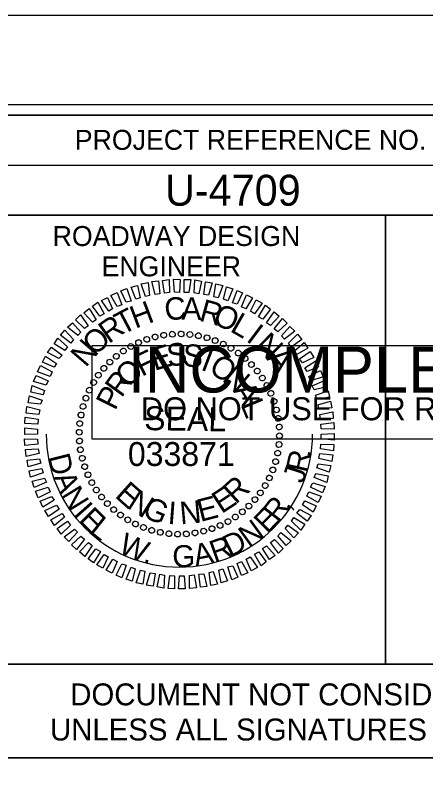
# Model space of a CAD drawing. Extents: x 1779926 to 1781610, y 620464 to 621564.
# Drawn here: x 1781400.2 to 1781503, y 621371.7 to 621564.2 of the extents above; entities that cross this region are included whole.
import ezdxf

# ---------------------------------------------------------------- set-up
doc = ezdxf.new("R2010")
doc.units = 0
for name, color, linetype in [('Old_Level_58', 7, 'Continuous'), ('Scratch_Level_0', 7, 'Continuous'), ('Sheet Cutting Line CELL', 7, 'Continuous'), ('Sheet Data Field CELL', 7, 'Continuous'), ('Sheet Plot Border Inside CELL', 7, 'Continuous'), ('Sheet Plot Border Outside CELL', 7, 'Continuous'), ('Sheet Professional Seal CELL', 7, 'Continuous'), ('Sheet Profile CELL', 7, 'Continuous'), ('Sheet Profile Grid Major CELL', 7, 'Continuous'), ('Sheet Profile Grid Minor CELL', 7, 'Continuous'), ('Sheet Sticker Exception Certification CELL', 7, 'Continuous'), ('Sheet Sticker Incomplete CELL', 7, 'Continuous')]:
    doc.layers.add(name, color=color, linetype=linetype)

msp = doc.modelspace()

# ---------------------------------------------------------------- linework, layer by layer
at = {"layer": 'Old_Level_58'}
msp.add_lwpolyline([(1781392.96, 621378.13), (1781592.95, 621378.13), (1781592.95, 621314.19), (1781392.96, 621314.19)], close=True, dxfattribs=at)
at = {"layer": 'Scratch_Level_0'}
msp.add_arc((1781441.32, 621459.29), 33.36, 180, 360, dxfattribs=at)
at = {"layer": 'Sheet Cutting Line CELL'}
msp.add_line((1781609.96, 621564.19), (1779925.96, 621564.19), dxfattribs=at)
at = {"layer": 'Sheet Plot Border Inside CELL'}
msp.add_lwpolyline([(1779938.96, 620486.64), (1781605.46, 620486.64), (1781605.46, 621541.74), (1779938.96, 621541.74)], close=True, dxfattribs=at)
at = {"layer": 'Sheet Plot Border Outside CELL'}
msp.add_lwpolyline([(1779925.96, 620464.19), (1781609.96, 620464.19), (1781609.96, 621564.19), (1779925.96, 621564.19)], close=True, dxfattribs=at)
at = {"layer": 'Sheet Professional Seal CELL'}
for p, q in [((1781439.57, 621484.34), (1781439.57, 621484.34)), ((1781441.77, 621484.39), (1781441.77, 621484.39)), ((1781433.12, 621483.04), (1781433.12, 621483.04)), ((1781435.22, 621483.64), (1781435.22, 621483.64)), ((1781437.42, 621484.04), (1781437.42, 621484.04)), ((1781443.97, 621484.24), (1781443.97, 621484.24)), ((1781446.12, 621483.89), (1781446.12, 621483.89)), ((1781448.22, 621483.44), (1781448.22, 621483.44)), ((1781450.32, 621482.74), (1781450.32, 621482.74)), ((1781429.17, 621481.24), (1781429.17, 621481.24)), ((1781431.12, 621482.24), (1781431.12, 621482.24)), ((1781452.32, 621481.84), (1781452.32, 621481.84)), ((1781454.27, 621480.84), (1781454.27, 621480.84)), ((1781425.52, 621478.84), (1781425.52, 621478.84)), ((1781427.27, 621480.09), (1781427.27, 621480.09)), ((1781456.07, 621479.59), (1781456.07, 621479.59)), ((1781423.87, 621477.34), (1781423.87, 621477.34)), ((1781457.82, 621478.24), (1781457.82, 621478.24)), ((1781459.37, 621476.74), (1781459.37, 621476.74)), ((1781422.37, 621475.79), (1781422.37, 621475.79)), ((1781460.87, 621475.09), (1781460.87, 621475.09)), ((1781421.02, 621474.04), (1781421.02, 621474.04)), ((1781462.12, 621473.34), (1781462.12, 621473.34)), ((1781419.77, 621472.24), (1781419.77, 621472.24)), ((1781463.27, 621471.44), (1781463.27, 621471.44)), ((1781418.77, 621470.29), (1781418.77, 621470.29)), ((1781464.27, 621469.49), (1781464.27, 621469.49)), ((1781417.87, 621468.29), (1781417.87, 621468.29)), ((1781465.07, 621467.49), (1781465.07, 621467.49)), ((1781417.17, 621466.19), (1781417.17, 621466.19)), ((1781465.67, 621465.39), (1781465.67, 621465.39)), ((1781416.72, 621464.09), (1781416.72, 621464.09)), ((1781466.07, 621463.19), (1781466.07, 621463.19)), ((1781416.37, 621461.94), (1781416.37, 621461.94)), ((1781416.22, 621459.74), (1781416.22, 621459.74)), ((1781466.37, 621461.04), (1781466.37, 621461.04)), ((1781416.27, 621457.54), (1781416.27, 621457.54)), ((1781441.32, 621459.29), (1781441.32, 621459.29)), ((1781466.42, 621458.84), (1781466.42, 621458.84)), ((1781466.27, 621456.64), (1781466.27, 621456.64)), ((1781416.57, 621455.39), (1781416.57, 621455.39)), ((1781465.92, 621454.49), (1781465.92, 621454.49)), ((1781416.97, 621453.19), (1781416.97, 621453.19)), ((1781465.47, 621452.39), (1781465.47, 621452.39)), ((1781417.57, 621451.09), (1781417.57, 621451.09)), ((1781464.77, 621450.29), (1781464.77, 621450.29)), ((1781418.37, 621449.09), (1781418.37, 621449.09)), ((1781463.87, 621448.29), (1781463.87, 621448.29)), ((1781419.37, 621447.14), (1781419.37, 621447.14)), ((1781462.87, 621446.34), (1781462.87, 621446.34)), ((1781420.52, 621445.24), (1781420.52, 621445.24)), ((1781461.62, 621444.54), (1781461.62, 621444.54)), ((1781421.77, 621443.49), (1781421.77, 621443.49)), ((1781460.27, 621442.79), (1781460.27, 621442.79)), ((1781423.27, 621441.84), (1781423.27, 621441.84)), ((1781424.82, 621440.34), (1781424.82, 621440.34)), ((1781458.77, 621441.24), (1781458.77, 621441.24)), ((1781426.57, 621438.99), (1781426.57, 621438.99)), ((1781455.37, 621438.49), (1781455.37, 621438.49)), ((1781457.12, 621439.74), (1781457.12, 621439.74)), ((1781428.37, 621437.74), (1781428.37, 621437.74)), ((1781430.32, 621436.74), (1781430.32, 621436.74)), ((1781451.52, 621436.34), (1781451.52, 621436.34)), ((1781453.47, 621437.34), (1781453.47, 621437.34)), ((1781432.32, 621435.84), (1781432.32, 621435.84)), ((1781434.42, 621435.14), (1781434.42, 621435.14)), ((1781436.52, 621434.69), (1781436.52, 621434.69)), ((1781438.67, 621434.34), (1781438.67, 621434.34)), ((1781445.22, 621434.54), (1781445.22, 621434.54)), ((1781447.42, 621434.94), (1781447.42, 621434.94)), ((1781449.52, 621435.54), (1781449.52, 621435.54)), ((1781440.87, 621434.19), (1781440.87, 621434.19)), ((1781443.07, 621434.24), (1781443.07, 621434.24))]:
    msp.add_line(p, q, dxfattribs=at)
for points in [[(1781437.62, 621494.59), (1781437.07, 621497.79), (1781438.77, 621497.99), (1781438.82, 621494.74)], [(1781440.12, 621494.84), (1781439.87, 621498.09), (1781441.52, 621498.04), (1781441.32, 621494.79)], [(1781442.52, 621494.79), (1781442.52, 621498.04), (1781444.17, 621497.99), (1781443.72, 621494.74)], [(1781445.02, 621494.64), (1781445.22, 621497.89), (1781446.87, 621497.59), (1781446.22, 621494.44)], [(1781430.42, 621493.09), (1781429.27, 621496.09), (1781430.82, 621496.54), (1781431.47, 621493.44)], [(1781432.82, 621493.74), (1781431.77, 621496.89), (1781433.47, 621497.24), (1781433.87, 621493.99)], [(1781435.22, 621494.29), (1781434.42, 621497.49), (1781436.07, 621497.64), (1781436.42, 621494.44)], [(1781447.42, 621494.24), (1781447.87, 621497.44), (1781449.52, 621497.19), (1781448.62, 621494.09)], [(1781449.97, 621493.69), (1781450.47, 621496.94), (1781452.17, 621496.54), (1781451.02, 621493.44)], [(1781452.37, 621493.04), (1781453.12, 621496.14), (1781454.67, 621495.64), (1781453.42, 621492.69)], [(1781425.77, 621491.24), (1781424.17, 621494.04), (1781425.72, 621494.74), (1781426.87, 621491.69)], [(1781427.97, 621492.29), (1781426.67, 621495.19), (1781428.17, 621495.79), (1781429.22, 621492.59)], [(1781454.62, 621492.14), (1781455.77, 621495.29), (1781457.17, 621494.69), (1781455.77, 621491.79)], [(1781456.87, 621491.19), (1781458.12, 621494.14), (1781459.67, 621493.44), (1781457.97, 621490.64)], [(1781421.42, 621488.79), (1781419.57, 621491.34), (1781420.87, 621492.29), (1781422.52, 621489.39)], [(1781423.62, 621490.04), (1781421.77, 621492.74), (1781423.32, 621493.54), (1781424.57, 621490.64)], [(1781459.17, 621490.04), (1781460.52, 621492.89), (1781462.02, 621492.04), (1781460.12, 621489.44)], [(1781419.52, 621487.29), (1781417.37, 621489.69), (1781418.72, 621490.74), (1781420.47, 621487.94)], [(1781461.12, 621488.69), (1781462.87, 621491.59), (1781464.17, 621490.54), (1781462.22, 621488.09)], [(1781417.52, 621485.74), (1781415.32, 621487.94), (1781416.52, 621489.14), (1781418.47, 621486.44)], [(1781463.17, 621487.19), (1781465.02, 621489.94), (1781466.32, 621488.84), (1781464.12, 621486.49)], [(1781465.07, 621485.64), (1781467.12, 621488.24), (1781468.32, 621487.04), (1781466.02, 621484.89)], [(1781415.87, 621483.99), (1781413.32, 621486.04), (1781414.57, 621487.19), (1781416.67, 621484.79)], [(1781414.12, 621482.09), (1781411.52, 621484.04), (1781412.62, 621485.34), (1781414.82, 621482.99)], [(1781466.87, 621483.89), (1781469.02, 621486.24), (1781470.22, 621485.04), (1781467.62, 621483.09)], [(1781468.62, 621482.09), (1781470.92, 621484.34), (1781471.97, 621482.99), (1781469.32, 621481.09)], [(1781412.62, 621480.19), (1781409.92, 621481.89), (1781410.87, 621483.34), (1781413.27, 621481.14)], [(1781411.12, 621478.19), (1781408.32, 621479.69), (1781409.32, 621481.09), (1781411.92, 621479.09)], [(1781470.12, 621480.14), (1781472.57, 621482.24), (1781473.52, 621480.79), (1781470.72, 621479.19)], [(1781409.92, 621476.04), (1781407.07, 621477.29), (1781407.82, 621478.84), (1781410.52, 621476.99)], [(1781471.42, 621478.09), (1781474.07, 621479.99), (1781475.02, 621478.49), (1781472.12, 621477.09)], [(1781472.72, 621475.89), (1781475.52, 621477.64), (1781476.17, 621476.09), (1781473.32, 621474.94)], [(1781408.92, 621473.74), (1781405.82, 621474.89), (1781406.57, 621476.44), (1781409.42, 621474.84)], [(1781473.72, 621473.74), (1781476.67, 621475.24), (1781477.32, 621473.64), (1781474.22, 621472.64)], [(1781407.92, 621471.54), (1781404.82, 621472.44), (1781405.47, 621473.99), (1781408.47, 621472.59)], [(1781407.17, 621469.14), (1781404.07, 621469.79), (1781404.42, 621471.44), (1781407.57, 621470.19)], [(1781474.62, 621471.39), (1781477.67, 621472.69), (1781478.22, 621471.14), (1781475.12, 621470.34)], [(1781475.42, 621468.99), (1781478.62, 621470.14), (1781478.92, 621468.49), (1781475.77, 621467.94)], [(1781406.52, 621466.74), (1781403.42, 621467.14), (1781403.77, 621468.84), (1781406.92, 621467.79)], [(1781476.02, 621466.59), (1781479.17, 621467.54), (1781479.47, 621465.84), (1781476.32, 621465.54)], [(1781406.12, 621464.19), (1781402.92, 621464.49), (1781403.12, 621466.19), (1781406.37, 621465.39)], [(1781405.87, 621461.79), (1781402.62, 621461.89), (1781402.72, 621463.54), (1781405.97, 621462.99)], [(1781476.47, 621464.19), (1781479.72, 621464.89), (1781479.87, 621463.19), (1781476.67, 621462.99)], [(1781476.77, 621461.79), (1781480.02, 621462.19), (1781480.12, 621460.49), (1781476.87, 621460.59)], [(1781405.82, 621459.29), (1781402.57, 621459.14), (1781402.57, 621460.84), (1781405.82, 621460.49)], [(1781476.82, 621459.29), (1781480.07, 621459.44), (1781480.07, 621457.74), (1781476.82, 621458.09)], [(1781405.87, 621456.79), (1781402.62, 621456.39), (1781402.52, 621458.09), (1781405.77, 621457.99)], [(1781406.17, 621454.39), (1781402.92, 621453.69), (1781402.77, 621455.39), (1781405.97, 621455.59)], [(1781476.77, 621456.79), (1781480.02, 621456.69), (1781479.92, 621455.04), (1781476.67, 621455.59)], [(1781476.52, 621454.39), (1781479.72, 621454.09), (1781479.52, 621452.39), (1781476.27, 621453.19)], [(1781406.62, 621451.99), (1781403.47, 621451.04), (1781403.17, 621452.74), (1781406.32, 621453.04)], [(1781476.12, 621451.84), (1781479.22, 621451.44), (1781478.87, 621449.74), (1781475.72, 621450.79)], [(1781407.22, 621449.59), (1781404.02, 621448.44), (1781403.72, 621450.09), (1781406.87, 621450.64)], [(1781408.02, 621447.19), (1781404.97, 621445.89), (1781404.42, 621447.44), (1781407.52, 621448.24)], [(1781475.47, 621449.44), (1781478.57, 621448.79), (1781478.22, 621447.14), (1781475.07, 621448.39)], [(1781408.92, 621444.84), (1781405.97, 621443.34), (1781405.32, 621444.94), (1781408.42, 621445.94)], [(1781474.72, 621447.04), (1781477.82, 621446.14), (1781477.17, 621444.59), (1781474.17, 621445.99)], [(1781473.72, 621444.84), (1781476.82, 621443.69), (1781476.07, 621442.14), (1781473.22, 621443.74)], [(1781409.92, 621442.69), (1781407.12, 621440.94), (1781406.47, 621442.49), (1781409.32, 621443.64)], [(1781472.72, 621442.54), (1781475.57, 621441.29), (1781474.82, 621439.74), (1781472.12, 621441.59)], [(1781411.22, 621440.49), (1781408.57, 621438.59), (1781407.62, 621440.09), (1781410.52, 621441.49)], [(1781471.52, 621440.39), (1781474.32, 621438.89), (1781473.32, 621437.49), (1781470.72, 621439.49)], [(1781412.52, 621438.44), (1781410.07, 621436.34), (1781409.12, 621437.79), (1781411.92, 621439.39)], [(1781470.02, 621438.39), (1781472.72, 621436.69), (1781471.77, 621435.24), (1781469.37, 621437.44)], [(1781414.02, 621436.49), (1781411.72, 621434.24), (1781410.67, 621435.59), (1781413.32, 621437.49)], [(1781468.52, 621436.49), (1781471.12, 621434.54), (1781470.02, 621433.24), (1781467.82, 621435.59)], [(1781415.77, 621434.69), (1781413.62, 621432.34), (1781412.42, 621433.54), (1781415.02, 621435.49)], [(1781466.77, 621434.59), (1781469.32, 621432.54), (1781468.07, 621431.39), (1781465.97, 621433.79)], [(1781417.57, 621432.94), (1781415.52, 621430.34), (1781414.32, 621431.54), (1781416.62, 621433.69)], [(1781465.12, 621432.84), (1781467.32, 621430.64), (1781466.12, 621429.44), (1781464.17, 621432.14)], [(1781419.47, 621431.39), (1781417.62, 621428.64), (1781416.32, 621429.74), (1781418.52, 621432.09)], [(1781421.52, 621429.89), (1781419.77, 621426.99), (1781418.47, 621428.04), (1781420.42, 621430.49)], [(1781463.12, 621431.29), (1781465.27, 621428.89), (1781463.92, 621427.84), (1781462.17, 621430.64)], [(1781423.47, 621428.54), (1781422.12, 621425.69), (1781420.62, 621426.54), (1781422.52, 621429.14)], [(1781459.02, 621428.54), (1781460.87, 621425.84), (1781459.32, 621425.04), (1781458.07, 621427.94)], [(1781461.22, 621429.79), (1781463.07, 621427.24), (1781461.77, 621426.29), (1781460.12, 621429.19)], [(1781425.77, 621427.39), (1781424.52, 621424.44), (1781422.97, 621425.14), (1781424.67, 621427.94)], [(1781428.02, 621426.44), (1781426.87, 621423.29), (1781425.47, 621423.89), (1781426.87, 621426.79)], [(1781456.87, 621427.34), (1781458.47, 621424.54), (1781456.92, 621423.84), (1781455.77, 621426.89)], [(1781430.27, 621425.54), (1781429.52, 621422.44), (1781427.97, 621422.94), (1781429.22, 621425.89)], [(1781432.67, 621424.89), (1781432.17, 621421.64), (1781430.47, 621422.04), (1781431.62, 621425.14)], [(1781449.82, 621424.84), (1781450.87, 621421.69), (1781449.17, 621421.34), (1781448.77, 621424.59)], [(1781452.22, 621425.49), (1781453.37, 621422.49), (1781451.82, 621422.04), (1781451.17, 621425.14)], [(1781454.67, 621426.29), (1781455.97, 621423.39), (1781454.47, 621422.79), (1781453.42, 621425.99)], [(1781435.22, 621424.34), (1781434.77, 621421.14), (1781433.12, 621421.39), (1781434.02, 621424.49)], [(1781437.62, 621423.94), (1781437.42, 621420.69), (1781435.77, 621420.99), (1781436.42, 621424.14)], [(1781440.12, 621423.79), (1781440.12, 621420.54), (1781438.47, 621420.59), (1781438.92, 621423.84)], [(1781442.52, 621423.74), (1781442.77, 621420.49), (1781441.12, 621420.54), (1781441.32, 621423.79)], [(1781445.02, 621423.99), (1781445.57, 621420.79), (1781443.87, 621420.59), (1781443.82, 621423.84)], [(1781447.42, 621424.29), (1781448.22, 621421.09), (1781446.57, 621420.94), (1781446.22, 621424.14)]]:
    msp.add_lwpolyline(points, close=True, dxfattribs=at)
for centre, major_axis in [((1781435.25, 621483.62), (-0.174, 0.699)), ((1781437.39, 621484.06), (-0.113, 0.711)), ((1781439.57, 621484.31), (-0.05, 0.718)), ((1781441.75, 621484.36), (0.013, 0.72)), ((1781443.94, 621484.23), (0.075, 0.716)), ((1781446.1, 621483.91), (0.137, 0.707)), ((1781431.11, 621482.2), (-0.293, 0.658)), ((1781433.15, 621483), (-0.234, 0.681)), ((1781448.23, 621483.4), (0.198, 0.692)), ((1781450.3, 621482.7), (0.258, 0.672)), ((1781452.31, 621481.83), (0.316, 0.647)), ((1781427.29, 621480.08), (-0.403, 0.597)), ((1781429.16, 621481.22), (-0.349, 0.63)), ((1781454.23, 621480.78), (0.371, 0.617)), ((1781425.53, 621478.78), (-0.453, 0.56)), ((1781456.06, 621479.58), (0.423, 0.582)), ((1781457.77, 621478.22), (0.472, 0.543)), ((1781423.89, 621477.33), (-0.5, 0.518)), ((1781459.36, 621476.71), (0.518, 0.5)), ((1781421.03, 621474.03), (-0.582, 0.423)), ((1781422.39, 621475.74), (-0.543, 0.472)), ((1781460.81, 621475.07), (0.56, 0.453)), ((1781419.82, 621472.2), (-0.617, 0.371)), ((1781462.11, 621473.31), (0.597, 0.403)), ((1781418.77, 621470.28), (-0.647, 0.316)), ((1781463.25, 621471.45), (0.63, 0.349)), ((1781417.9, 621468.28), (-0.672, 0.258)), ((1781464.23, 621469.49), (0.658, 0.293)), ((1781417.21, 621466.2), (-0.692, 0.198)), ((1781465.03, 621467.45), (0.681, 0.234)), ((1781465.65, 621465.35), (0.699, 0.174)), ((1781416.7, 621464.07), (-0.707, 0.137)), ((1781466.09, 621463.21), (0.711, 0.113)), ((1781416.37, 621461.91), (-0.716, 0.075)), ((1781466.33, 621461.04), (0.718, 0.05)), ((1781416.24, 621459.72), (-0.72, 0.013)), ((1781466.39, 621458.85), (0.72, -0.013)), ((1781416.3, 621457.54), (-0.718, -0.05)), ((1781466.26, 621456.67), (0.716, -0.075)), ((1781416.54, 621455.36), (-0.711, -0.113)), ((1781416.98, 621453.22), (-0.699, -0.174)), ((1781465.93, 621454.5), (0.707, -0.137)), ((1781417.6, 621451.12), (-0.681, -0.234)), ((1781465.42, 621452.37), (0.692, -0.198)), ((1781418.4, 621449.09), (-0.658, -0.293)), ((1781464.73, 621450.3), (0.672, -0.258)), ((1781419.38, 621447.13), (-0.63, -0.349)), ((1781463.86, 621448.29), (0.647, -0.316)), ((1781420.52, 621445.26), (-0.597, -0.403)), ((1781462.81, 621446.37), (0.617, -0.371)), ((1781421.82, 621443.5), (-0.56, -0.453)), ((1781461.61, 621444.55), (0.582, -0.423)), ((1781423.27, 621441.87), (-0.518, -0.5)), ((1781458.74, 621441.25), (0.5, -0.518)), ((1781460.24, 621442.83), (0.543, -0.472)), ((1781424.86, 621440.36), (-0.472, -0.543)), ((1781457.1, 621439.8), (0.453, -0.56)), ((1781426.57, 621439), (-0.423, -0.582)), ((1781428.4, 621437.79), (-0.371, -0.617)), ((1781453.47, 621437.35), (0.349, -0.63)), ((1781455.34, 621438.49), (0.403, -0.597)), ((1781430.32, 621436.75), (-0.316, -0.647)), ((1781432.33, 621435.87), (-0.258, -0.672)), ((1781449.48, 621435.57), (0.234, -0.681)), ((1781451.52, 621436.38), (0.293, -0.658)), ((1781434.4, 621435.18), (-0.198, -0.692)), ((1781436.53, 621434.67), (-0.137, -0.707)), ((1781438.69, 621434.34), (-0.075, -0.716)), ((1781440.88, 621434.21), (-0.013, -0.72)), ((1781443.07, 621434.27), (0.05, -0.718)), ((1781445.24, 621434.52), (0.113, -0.711)), ((1781447.38, 621434.95), (0.174, -0.699))]:
    msp.add_ellipse(centre, major_axis=major_axis, ratio=0.999708, dxfattribs=at)
at = {"layer": 'Sheet Profile CELL'}
for p, q in [((1781392.91, 621526.64), (1781592.96, 621526.64)), ((1781492.96, 621514.14), (1781492.96, 621401.69))]:
    msp.add_line(p, q, dxfattribs=at)
for points in [[(1781592.96, 621539.19), (1780092.96, 621539.19), (1780092.96, 620489.19), (1781592.96, 620489.19)], [(1781392.91, 621539.19), (1781592.96, 621539.19), (1781592.96, 621514.14), (1781392.91, 621514.14)], [(1781392.91, 621514.14), (1781492.96, 621514.14), (1781492.96, 621401.64), (1781392.91, 621401.64)], [(1781492.96, 621514.14), (1781592.96, 621514.14), (1781592.96, 621401.64), (1781492.96, 621401.64)]]:
    msp.add_lwpolyline(points, close=True, dxfattribs=at)
at = {"layer": 'Sheet Profile Grid Major CELL'}
msp.add_lwpolyline([(1781142.96, 621039.19), (1781192.96, 621039.19), (1781192.96, 621539.19), (1781242.96, 621539.19), (1781242.96, 621039.19), (1781292.96, 621039.19), (1781292.96, 621539.19), (1781342.96, 621539.19), (1781342.96, 621039.19), (1781392.96, 621039.19), (1781392.96, 621539.19), (1781419.26, 621539.19)], dxfattribs=at)
at = {"layer": 'Sheet Sticker Exception Certification CELL'}
for p, q in [((1781392.91, 621401.64), (1781592.95, 621401.64)), ((1781392.91, 621401.64), (1781592.95, 621401.64)), ((1781592.95, 621378.14), (1781392.91, 621378.14)), ((1781592.95, 621378.14), (1781392.91, 621378.14))]:
    msp.add_line(p, q, dxfattribs=at)
at = {"layer": 'Sheet Sticker Incomplete CELL'}
msp.add_lwpolyline([(1781419.48, 621457.99), (1781419.48, 621481.49), (1781566.48, 621481.49), (1781566.48, 621457.99)], close=True, dxfattribs=at)

# ---------------------------------------------------------------- texts
at = {"layer": 'Sheet Data Field CELL'}
msp.add_text('U-4709', height=7.75, dxfattribs=at).set_placement((1781437.72, 621516.5))
at = {"layer": 'Sheet Professional Seal CELL'}
for s, height, rotation, p in [('H', 5.64, 20.6195, (1781430.27, 621485.64)), ('C', 5.64, 6.2199, (1781437.87, 621487.64)), ('A', 5.64, 359.0203, (1781441.82, 621487.94)), ('R', 5.64, 344.6211, (1781446.02, 621487.74)), ('T', 5.64, 27.8198, (1781427.02, 621483.99)), ('O', 5.64, 337.4212, (1781449.37, 621486.99)), ('R', 5.64, 35.0205, (1781423.62, 621481.79)), ('L', 5.64, 330.2209, (1781453.77, 621485.14)), ('I', 5.64, 323.0201, (1781457.82, 621482.74)), ('O', 5.64, 42.2217, (1781420.17, 621478.69)), ('N', 5.64, 315.8189, (1781459.97, 621481.19)), ('N', 5.64, 49.4235, (1781417.87, 621475.79)), ('F', 5.64, 25.967, (1781431.87, 621473.59)), ('E', 5.64, 16.6111, (1781435.07, 621475.09)), ('S', 5.64, 7.2556, (1781438.52, 621476.14)), ('S', 5.64, 357.9004, (1781442.12, 621476.19)), ('I', 5.64, 339.1896, (1781446.42, 621475.49)), ('O', 5.64, 329.8335, (1781448.42, 621474.79)), ('A', 5.64, 308.6172, (1781462.92, 621478.24)), ('O', 5.64, 44.6812, (1781428.57, 621470.64)), ('N', 5.64, 320.4766, (1781451.77, 621472.79)), ('R', 5.64, 54.0397, (1781426.82, 621468.19)), ('P', 5.64, 63.3989, (1781425.22, 621464.99)), ('A', 5.64, 301.7603, (1781454.62, 621470.19)), ('L', 5.64, 292.4008, (1781456.57, 621466.74)), ('SEAL', 5.998, 359, (1781432.47, 621460.29)), ('R', 5.64, 42.4814, (1781455.42, 621441.54)), ('E', 5.64, 318.2769, (1781424.92, 621443.64)), ('E', 5.64, 33.1241, (1781451.87, 621439.19)), ('N', 5.64, 327.634, (1781427.92, 621440.94)), ('G', 5.64, 336.9902, (1781431.72, 621438.69)), ('I', 5.64, 355.7012, (1781438.27, 621436.79)), ('N', 5.64, 5.0564, (1781441.62, 621436.64)), ('E', 5.64, 14.4118, (1781446.57, 621437.24))]:
    msp.add_text(s, height=height, rotation=rotation, dxfattribs=at).set_placement(p)
at = {"layer": 'Sheet Profile CELL'}
for s, height, p in [('PROJECT REFERENCE NO.', 5.0001, (1781415.12, 621530.5)), ('ROADWAY DESIGN', 5.0001, (1781409.57, 621506.4)), ('ENGINEER', 5, (1781421.82, 621498.8))]:
    msp.add_text(s, height=height, dxfattribs=at).set_placement(p)
at = {"layer": 'Sheet Profile Grid Minor CELL'}
msp.add_text('033871', height=5.998, dxfattribs=at).set_placement((1781428.42, 621451.28))
for s, rotation, p in [('D', 284.2682, (1781408.32, 621453.64)), ('R', 77.3541, (1781473.29, 621449.39)), ('.', 84.2805, (1781474.25, 621453.31)), ('J', 72.4855, (1781472.33, 621446.71)), ('A', 293.4128, (1781409.64, 621448.47)), ('N', 301.5986, (1781411.5, 621444.07)), ('I', 311.5304, (1781414.57, 621439.16)), ('R', 52.3788, (1781466.12, 621436.81)), ('E', 315.0508, (1781415.86, 621437.56)), ('E', 45.7958, (1781463.38, 621434.12)), (',', 59.3052, (1781468.65, 621439.97)), ('L', 321.6338, (1781418.52, 621434.78)), ('N', 35.8641, (1781458.7, 621430.69)), ('W', 336.8891, (1781425.77, 621429.65)), ('D', 26.7195, (1781453.94, 621428.29)), ('R', 19.793, (1781450.11, 621426.99)), ('G', 1.6755, (1781439.63, 621425.86)), ('A', 11.6072, (1781445.42, 621426.07)), ('.', 348.4952, (1781432.05, 621427.12))]:
    msp.add_text(s, height=5.5, rotation=rotation, dxfattribs=at).set_placement(p)
at = {"layer": 'Sheet Sticker Exception Certification CELL'}
for s, p in [('DOCUMENT NOT CONSIDERED FINAL', (1781413.98, 621391.3)), ('DOCUMENT NOT CONSIDERED FINAL', (1781413.98, 621391.3)), ('UNLESS ALL SIGNATURES COMPLETED', (1781408.91, 621382.5)), ('UNLESS ALL SIGNATURES COMPLETED', (1781408.91, 621382.5))]:
    msp.add_text(s, height=5.5, dxfattribs=at).set_placement(p)
at = {"layer": 'Sheet Sticker Incomplete CELL'}
for s, height, p in [('INCOMPLETE PLANS', 11.52, (1781428.43, 621469.69)), ('DO NOT USE FOR R/W ACQUISITION', 5.76, (1781431.68, 621462.74))]:
    msp.add_text(s, height=height, dxfattribs=at).set_placement(p)

doc.saveas('drawing.dxf')
